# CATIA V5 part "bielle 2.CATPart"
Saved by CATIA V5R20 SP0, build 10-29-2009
Part number: bielle 2
Bounding box of the stored display mesh (mm): x 0 to 5, y -76.416 to 38.584, z 30.028 to 49.972
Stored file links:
  E:\EDELI\wjacquemont\Edeli_2012_122_wjacquemont\bielle 2.CATPart
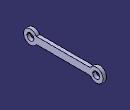
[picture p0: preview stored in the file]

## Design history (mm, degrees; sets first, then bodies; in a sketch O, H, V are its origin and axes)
Parameters
  `Longueur bièle` = 95 mm
Body1 (main body)
  Sketch1 on yz-plane, origin (0, 0, 0), H (0, 1, 0), V (0, 0, 1)
    line L1 (-57.7553, 45) -> (19.9242, 45)
    line L2 (-57.7553, 35) -> (19.9242, 35)
    axis line L3 (-76.4155, 40) -> (33.5845, 40)
    point P5 (-76.4155, 40)
    arc A1 centre (-66.4155, 40) radius 10 from (-57.7553, 45) to (-57.7553, 35) ccw
    point P7 (-66.4155, 40)
    arc A2 centre (28.5845, 40) radius 10 from (19.9242, 35) to (19.9242, 45) ccw
    point P8 (28.5845, 40)
    circle A3 centre (28.5845, 40) radius 5
    circle A4 centre (-66.4155, 40) radius 5
    distance L2 L1 = 10
    radius A1 = 10
    radius A2 = 10
    distance P8 P7 = 95 {= `Longueur bièle`}
    radius A3 = 5
    radius A4 = 5
    horizontal: L1 H, L2 H, L3 H
    coincidence: A1 P5, P7 L3, P8 L3
    symmetry: L2 L1 L3
  Pad1: profile Sketch1, direction (1, 0, 0), length 5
